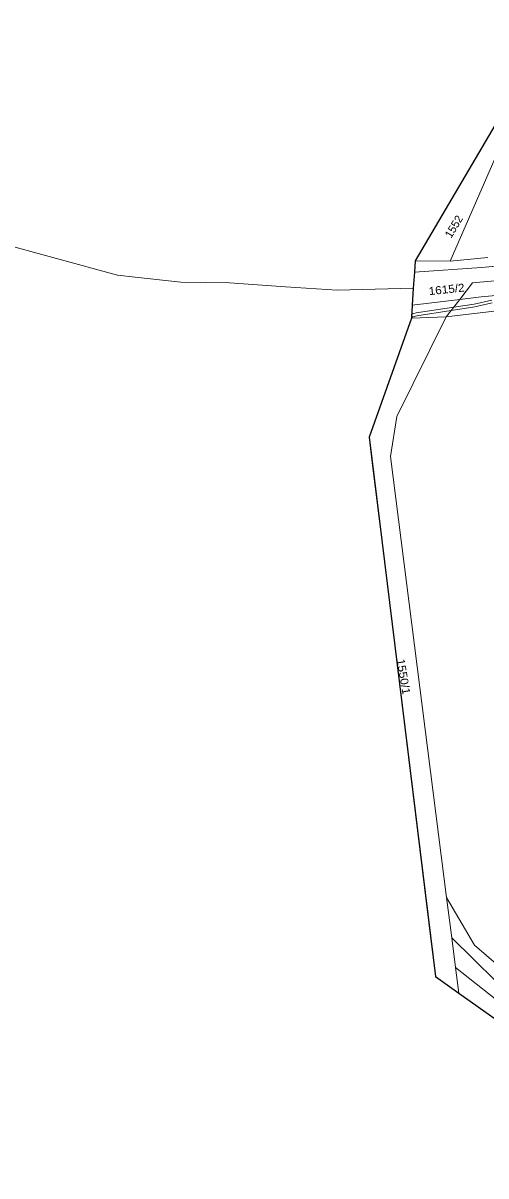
# Model space of a CAD drawing. Extents: x -686207 to -681951, y -1020493 to -1017811.
# Drawn here: x -684615.2 to -684516.8, y -1019707.1 to -1019462.2 of the extents above; entities that cross this region are included whole.
import ezdxf

# ---------------------------------------------------------------- set-up
doc = ezdxf.new("R2010")
doc.units = 0
doc.header["$LTSCALE"] = 0.4
for name, color, linetype, lineweight in [('1', 7, 'Continuous', 13), ('13', 7, 'Continuous', 13), ('22', 7, 'Continuous', 13), ('24', 7, 'Continuous', 25), ('4', 7, 'Continuous', 13)]:
    doc.layers.add(name, color=color, linetype=linetype, lineweight=lineweight)
doc.layers.add('2', color=7, linetype='Continuous')

msp = doc.modelspace()

# ---------------------------------------------------------------- linework, layer by layer
at = {"layer": '1'}
for p, q in [((-684522.24, -1019496.29), (-684512.05, -1019478.99)), ((-684524.43, -1019512.77), (-684513.25, -1019487.11)), ((-684531.89, -1019512.67), (-684522.24, -1019496.29)), ((-684532.04, -1019515.06), (-684531.89, -1019512.67)), ((-684524.43, -1019512.77), (-684531.89, -1019512.67)), ((-684524.43, -1019512.77), (-684516.43, -1019511.96)), ((-684490.8, -1019520.39), (-684525.29, -1019524.6)), ((-684541.65, -1019550.12), (-684532.66, -1019524.82)), ((-684532.59, -1019523.62), (-684532.66, -1019524.82)), ((-684532.66, -1019524.82), (-684525.29, -1019524.6)), ((-684528.44, -1019657.32), (-684538.53, -1019575.42)), ((-684527.53, -1019664.73), (-684528.44, -1019657.32)), ((-684492.41, -1019687.22), (-684523.29, -1019662.77)), ((-684522.6, -1019668.21), (-684527.53, -1019664.73)), ((-684522.6, -1019668.21), (-684492.12, -1019689.8))]:
    msp.add_line(p, q, dxfattribs=at)
for points in [[(-684532.59, -1019523.62), (-684532.49, -1019522.07), (-684532.26, -1019518.47), (-684532.04, -1019515.06)], [(-684525.29, -1019524.6), (-684522.39, -1019520.87), (-684519.65, -1019517.34), (-684509.36, -1019516.42), (-684498.93, -1019518.65), (-684490.8, -1019520.39)], [(-684525.18, -1019647.91), (-684537.1, -1019554.2), (-684535.78, -1019545.74), (-684525.29, -1019524.6)], [(-684538.53, -1019575.42), (-684540.84, -1019556.68), (-684541.65, -1019550.12)], [(-684522.6, -1019668.21), (-684523.29, -1019662.77), (-684524.09, -1019656.5), (-684525.18, -1019647.91)], [(-684525.18, -1019647.91), (-684519.28, -1019658.03), (-684491.79, -1019681.72)], [(-684490.1, -1019686.01), (-684510.09, -1019670.21), (-684524.09, -1019656.5)]]:
    msp.add_lwpolyline(points, dxfattribs=at)
at = {"layer": '13'}
msp.add_lwpolyline([(-684515.6, -1019521.01), (-684519.3, -1019521.87), (-684523.68, -1019522.54), (-684531.62, -1019523.74), (-684532.61, -1019524), (-684532.66, -1019524.82), (-684532.38, -1019524.59), (-684531.5, -1019524.33), (-684524.22, -1019523.23), (-684519.2, -1019522.47), (-684515.5, -1019521.61)], dxfattribs=at)
at = {"layer": '22'}
msp.add_lwpolyline([(-684532.26, -1019518.47), (-684548.425, -1019518.87), (-684559.44, -1019518.17), (-684571.297, -1019517.313), (-684581.672, -1019517.211), (-684591.388, -1019516.131), (-684595.124, -1019515.744), (-684634.03, -1019505.115)], dxfattribs=at)
at = {"layer": '24'}
msp.add_lwpolyline([(-684500.14, -1019451.56), (-684512.05, -1019478.99), (-684531.89, -1019512.67), (-684532.04, -1019515.06), (-684532.26, -1019518.47), (-684532.49, -1019522.07), (-684532.66, -1019524.82), (-684541.65, -1019550.12), (-684527.53, -1019664.73), (-684522.6, -1019668.21), (-684492.12, -1019689.8), (-684490.48, -1019690.96), (-684484.2, -1019695.03), (-684475.13, -1019700.9), (-684470.07, -1019701.85), (-684450.86, -1019705.44), (-684423.56, -1019707.07), (-684414.98, -1019706.64), (-684406.56, -1019701.65), (-684379.46, -1019663.55), (-684362.26, -1019668.43), (-684353.33, -1019670.49), (-684310.5, -1019679.94)], dxfattribs=at)
at = {"layer": '4'}
for p, q in [((-684517.76, -1019514.11), (-684510.01, -1019513.42)), ((-684532.04, -1019515.06), (-684517.76, -1019514.11)), ((-684532.49, -1019522.07), (-684522.39, -1019520.87))]:
    msp.add_line(p, q, dxfattribs=at)
msp.add_lwpolyline([(-684522.39, -1019520.87), (-684517.85, -1019520.33), (-684498.93, -1019518.65)], dxfattribs=at)

# ---------------------------------------------------------------- texts
at = {"layer": '2'}
msp.add_text('1552', height=1.7, rotation=59, dxfattribs=at).set_placement((-684524.222, -1019507.996))
at = {"layer": '2', "width": 1.1}
for s, rotation, p in [('1615/2', 6, (-684528.901, -1019519.965)), ('1550/1', 280, (-684535.831, -1019597.372))]:
    msp.add_text(s, height=1.7, rotation=rotation, dxfattribs=at).set_placement(p)

doc.saveas('drawing.dxf')
